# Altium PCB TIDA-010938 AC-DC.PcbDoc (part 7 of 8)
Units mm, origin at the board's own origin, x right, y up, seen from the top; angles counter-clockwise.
Board outline 280 x 180.15 mm, 4 copper layers (Top Layer, Layer 1, Layer 2, Bottom Layer), stack 1.787 mm thick; 723 components, 427 nets, 2244 pads, 2295 vias.
Unrouted connection lines stored in the file: 17.
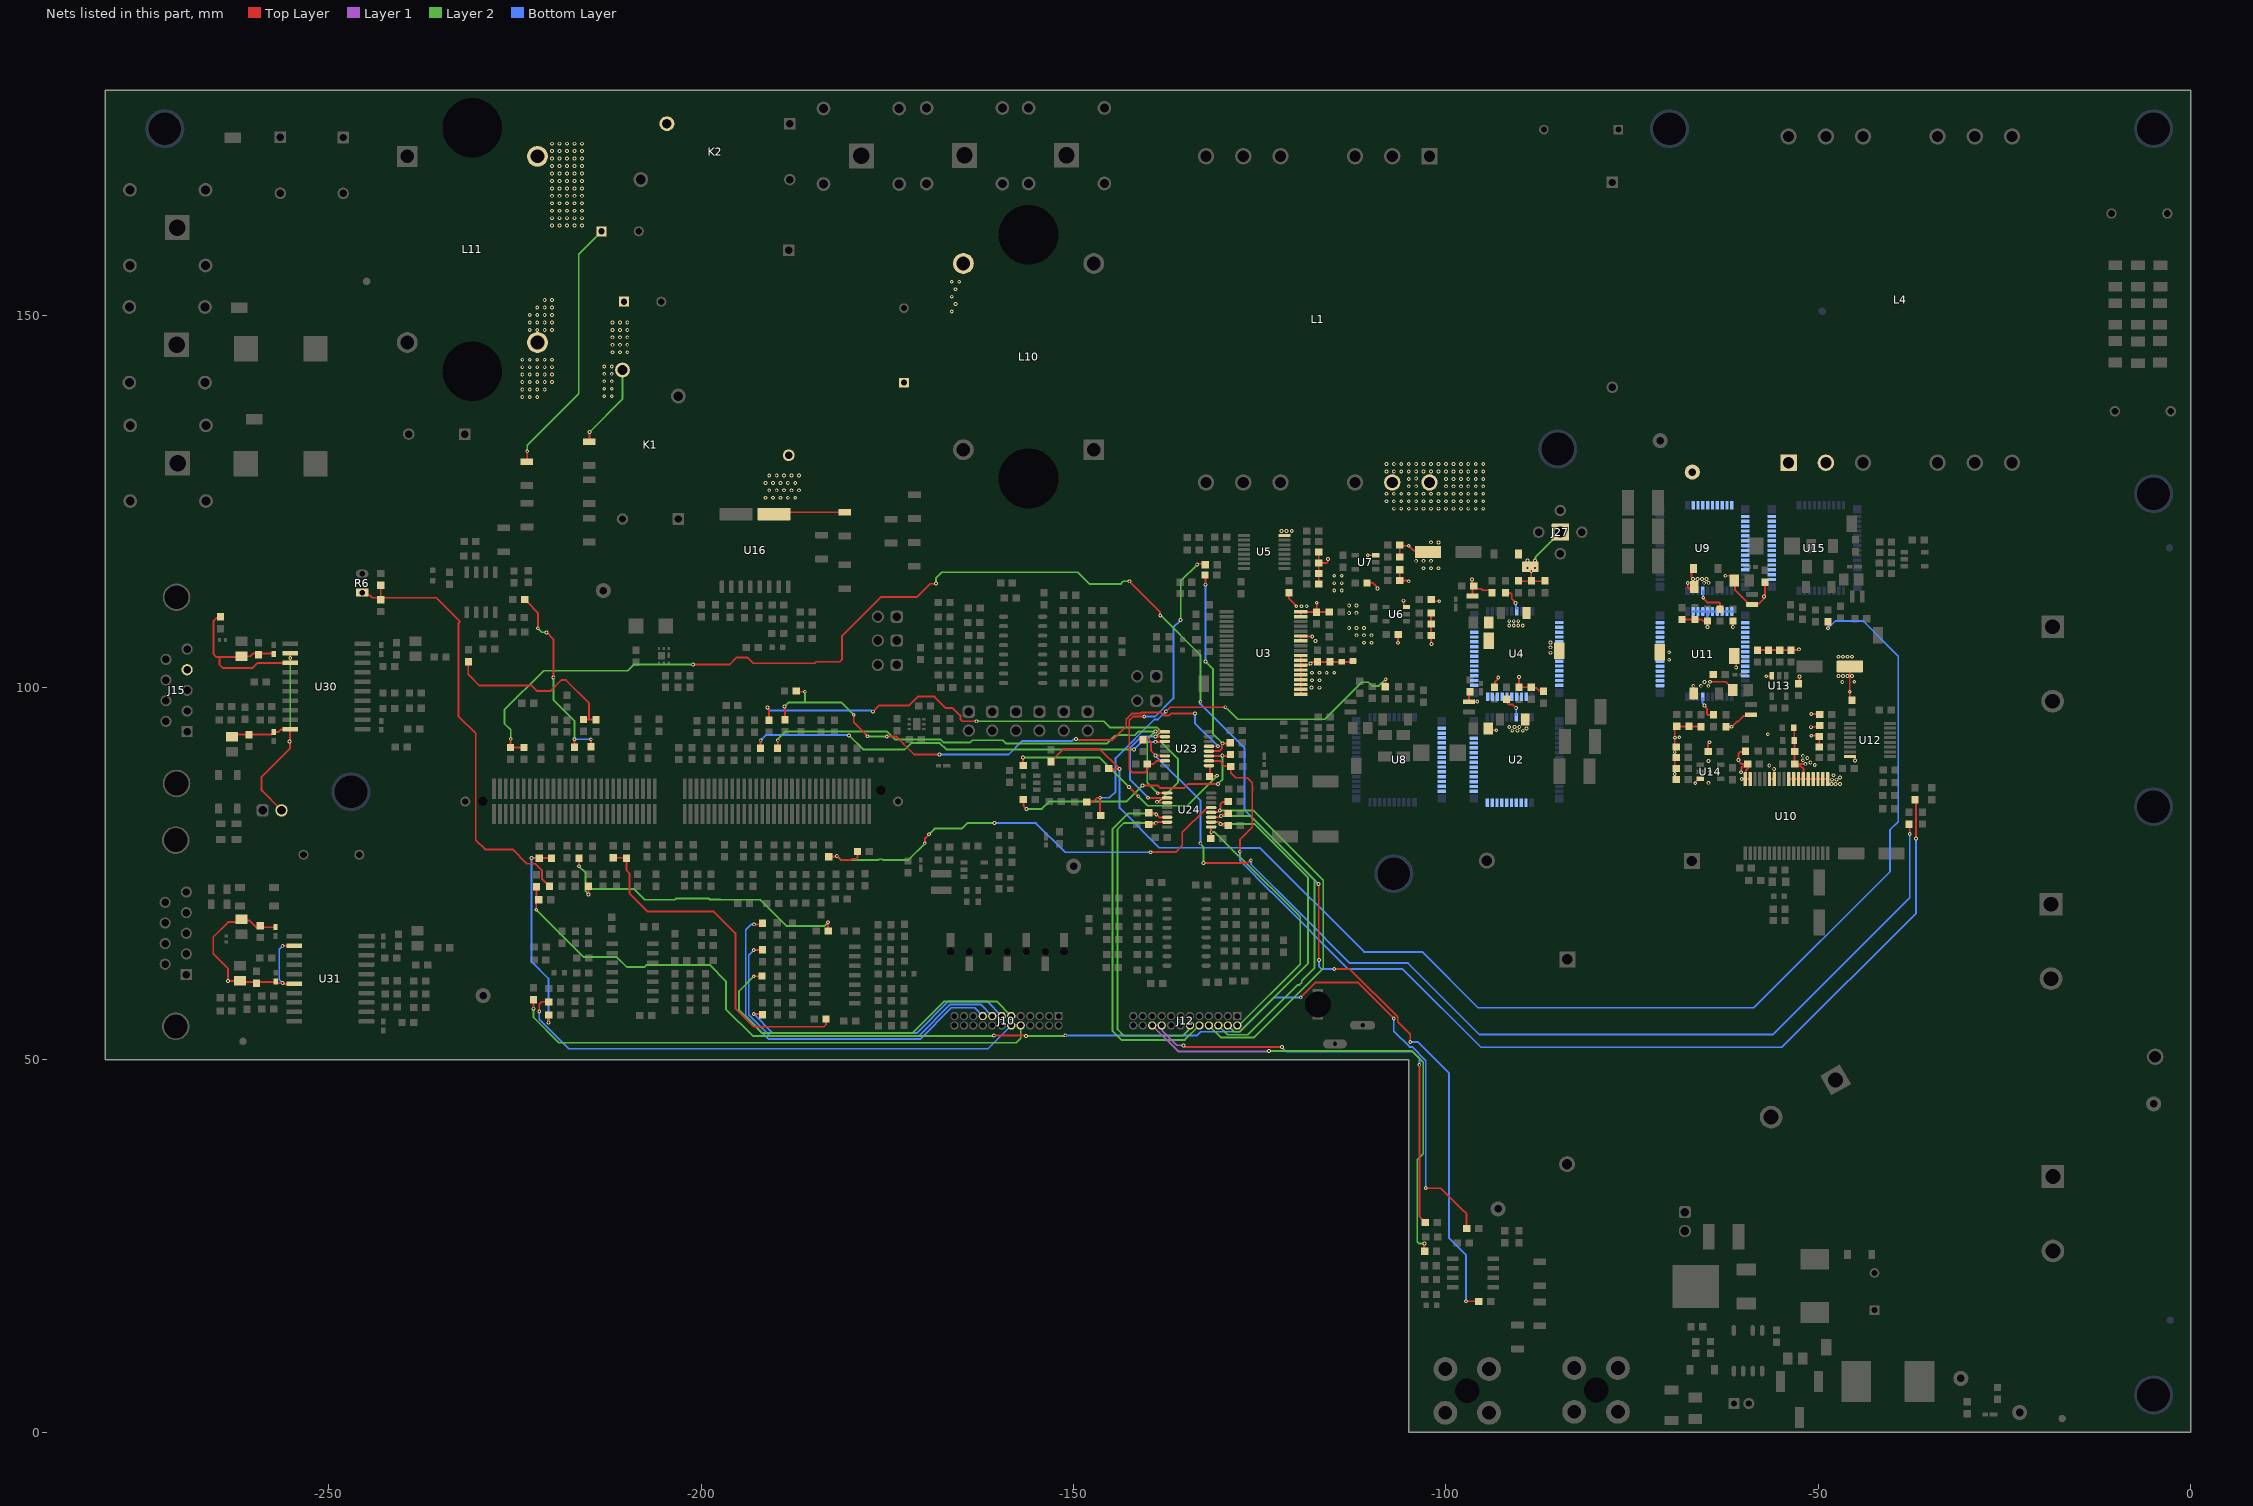
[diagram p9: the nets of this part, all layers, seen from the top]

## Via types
v1: diameter 0.508, hole 0.254, Top Layer to Bottom Layer, tented both sides, 2041 vias
v2: diameter 0.508, hole 0.254, Top Layer to Bottom Layer, 252 vias
v3: diameter 0.5, hole 0.2, Top Layer to Bottom Layer, 2 vias

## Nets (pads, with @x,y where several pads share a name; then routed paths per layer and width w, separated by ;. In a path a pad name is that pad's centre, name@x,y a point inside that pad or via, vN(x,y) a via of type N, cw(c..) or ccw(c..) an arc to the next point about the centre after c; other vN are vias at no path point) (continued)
SW_1: C11.2 C12.2 C13.1 C14.1 C15.2 C16.1 C17.1 C19.1 C20.2 C21.2 C24.2 C25.1 C26.2 C27.1 C28.2 C32.1 C33.1 C34.1 C35.1 C39.2 C40.2 C43.2 C47.2 C245.1 C246.1 C247.1 C248.1 D2.2 J27.1 L1.11 L1.12 L2.1 L3.1 R10.1 R15.2 R17.1 R30.1 R42.1 R237.1 R328.1 R329.1 R330.1 TP9.1 TP17.1 U2.18 U2.19 U2.20 U2.21 U2.22 U2.23 U2.24 U2.25 U2.26 U2.28 U2.29 U2.30 U2.31 U2.32 U2.33 U2.34 U2.35 U2.36 U2.37 U2.38 U2.39 U3.19 U3.20 U3.21 U3.22 U3.23 U3.24 U3.25 U3.26 U3.27 U3.30 U3.31 U3.35 U3.36 U4.18 U4.19 U4.20 U4.21 U4.22 U4.23 U4.24 U4.25 U4.26 U4.28 U4.29 U4.30 U4.31 U4.32 U4.33 U4.34 U4.35 U4.36 U4.37 U4.38 U4.39 U5.8 U6.3 U7.3 U8.2 U8.3 U8.4 U8.5 U8.6 U8.7 U8.8 U8.9 U8.10 U8.11 U8.12 U8.13 U8.14 U8.15 | length 73.3
  Top Layer w0.25: C39.2@-121.1,112.7 -121.1,111.95 -120.1,110.95 v1(-120.1,110.9) ; U3.27@-119.5,104.3 U3.26@-119.5,103.65 U3.25@-119.5,103 ; U3.35@-119.5,109.5 U3.36@-119.5,110.05 ; U3.36@-119.5,110.15 -117.55,110.15 C21.2@-117.475,110.225 ; U3.19@-119.425,99.175 -119.475,99.175 -119.5,99.2 U3.20@-119.5,99.75 U3.21@-119.5,100.4 U3.22@-119.5,101.05 U3.23@-119.5,101.7 U3.24@-119.5,102.35 U3.25@-119.5,103 ; U3.30@-119.425,106.3 -119.45,106.3 -119.5,106.35 U3.31@-119.5,106.9 -119.462,106.862 -117.962,106.862 v1@-117.95,106.85 ; v1(-117.35,111.375) -117.35,110.325 C21.2@-117.25,110.225 ; C21.2@-117.25,110.125 -115.775,110.125 R15.2@-115.725,110.175 ; C35.1@-117.075,118.2 C34.1@-117.075,116.7 ; C32.1@-117.05,113.9 -117.075,113.925 C33.1@-117.075,115.3 C34.1@-117.075,116.7 ; C16.1@-116.925,103.425 C17.1@-115.575,103.425 C19.1@-112.475,103.425 ; C16.1@-116.925,103.475 -116.979,103.421 -117.979,103.421 -118.35,103.05 -119.45,103.05 U3.25@-119.5,103 ; v1@-115.8,117.325 -115.874,117.251 -115.874,116.876 -116.05,116.7 C34.1@-117.075,116.7 ; C47.2@-110.6,114.05 -109.825,114.05 -109.249,113.474 -109.249,113.349 v1(-109.2,113.3) ; v1(-110.5,117.75) U7.3@-109.45,117.75 ; v1@-106.45,106.075 -106.45,107.05 C43.2@-106.4,107.1 ; C248.1@-106.2,117.525 R330.1@-106.2,119.125 -106.1,119.025 v1@-105.05,119.025 ; C247.1@-106.15,115.75 -106.2,115.7 R329.1@-106.2,114.35 -105.17,114.35 -105.07,114.25 v1(-105,114.25) ; v1(-105.72,111.65) -105.672,111.602 -105.672,110.975 -105.624,110.975 -105.449,110.8 U6.3@-105.3,110.8 ; v1(-105,119.025) -104.379,118.404 -102.604,118.404 C40.2@-102.4,118.2 ; C246.1@-102,110 C245.1@-102,108.5 R237.1@-102,107 -102,105.97 -101.98,105.95 v1@-101.95,105.95 ; R328.1@-102,111.8 -101.775,111.575 -101,111.575 v1@-100.925,111.65 ; R17.1@-96.8,99.4 -96.9,99.3 L2.1@-96.9,98.075 -96.887,98.088 -95.812,98.088 v1(-95.8,98.1) ; R17.1@-96.7,99.4 R17.1@-96.605,99.305 ; v1(-96.5,114.5) -96.5,113.8 R42.1@-96.3,113.6 ; L3.1@-96.45,112.275 -96.45,113.45 R42.1@-96.3,113.6 ; C28.2@-94.325,108.659 C28.2@-94.284,108.7 ; C15.2@-94.309,94.5 -94.059,94.25 v1(-93.254,94.25) ; C26.2@-93.8,112.7 -94.15,113.051 -95.046,113.051 -95.245,113.25 -95.95,113.25 R42.1@-96.3,113.6 ; C13.1@-93.475,100.05 -93.401,100.124 -93.401,100.779 v1@-92.992,101.187 ; D2.2@-90.36,117.998 D2.2@-90.262,117.9 ; R30.1@-90.25,114.325 -90.175,114.25 C27.1@-88.175,114.25 ; v1(-90.2,101.4) -90.2,100.225 -90.3,100.125 R10.1@-90.2,100.025 C14.1@-88.625,100.025 ; C11.2@-89.35,95.7 C11.2@-89.25,95.6 ; C24.2@-89.25,109.925 C24.2@-89.2,109.975 C24.2@-89.075,109.85 ; C14.1@-88.55,100.025 -88.475,99.95 -87.9,99.95 -87.55,99.6 -86.75,99.6 C12.2@-86.7,99.55 ; v1(-88.55,115.65) -88.55,114.625 C27.1@-88.175,114.25 ; C25.1@-86.75,114.25 C27.1@-88.175,114.25
  Layer 2 w0.25: v1(-88.046,117.051) -87.997,117.1 -87.997,117.511 J27.1@-84.654,120.853
  other v1: -91.1,94.2 -90.4,94.2 -89.7,94.2 -89.2,94.5 -91.5,94.7 -90.8,94.7 -90.15,94.7 -116.994,99.969 -118.048,100.002 -117.994,100.969 -116.994,100.969 -92.981,101.323 -117.994,101.969 -116.994,101.969 -116.019,101.969 -114.994,101.969 -118.175,103.2 -101.95,105.85 -111,106 -110,106 -106.45,106 -117.5,106.25 -117.95,106.825 -112,107 -111,107 -110,107 -113,108 -112,108 -111,108 -91.5,108.3 -90.9,108.3 -90.3,108.3 -89.7,108.3 -91.5,108.9 -90.9,108.9 -90.3,108.9 -113,110 -112.004,110.018 -119.4,110.9 -118.7,110.9 -113,111 -112,111 -100.9,111.575 -115,113 -114,113 -115,114 -114,114 -115,115 -114,115 -103,116 -102,116 -101,116 -89.046,116.051 -88.046,116.051 -104,117 -103,117 -102,117 -89.046,117.051 -115.825,117.25 -101.004,119.454 -102.028,119.482 -122.1,121 -121.4,121 -120.7,121 -107,124 -106,124 -105,124 -104,124 -103,124 -102,124 -101,124 -100,124 -99,124 -98,124 -97,124 -96,124 -95,124 -108,125 -107,125 -106,125 -105,125 -104,125 -103,125 -102,125 -101,125 -100,125 -99,125 -98,125 -97,125 -96,125 -95,125 -108,126 -107,126 -106,126 -105,126 -104,126 -103,126 -102,126 -101,126 -100,126 -99,126 -98,126 -97,126 -96,126 -95,126 -105,127 -104,127 -100,127 -99,127 -98,127 -97,127 -96,127 -95,127 -105,128 -100,128 -99,128 -98,128 -97,128 -96,128 -95,128 -104.002,128.039 -108,129 -107,129 -106,129 -105,129 -104,129 -103,129 -102,129 -101,129 -100,129 -99,129 -98,129 -97,129 -96,129 -95,129 -108,130 -107,130 -106,130 -105,130 -104,130 -103,130 -102,130 -101,130 -100,130 -99,130 -98,130 -97,130 -96,130 -95,130
SW_2: C44.2 C48.1 C57.2 C58.2 C59.1 C60.1 C61.2 C62.1 C63.1 C65.2 C66.2 C69.2 C70.1 C71.1 C72.1 C73.2 C77.1 C78.1 C79.1 C80.1 C85.1 C89.1 C91.2 C188.2 C240.2 C249.1 C250.1 D8.2 L4.1 L4.2 L6.1 L7.1 R33.1 R34.1 R44.1 R49.2 R51.1 R52.1 R60.1 R331.1 R332.1 TP10.1 TP18.1 U9.18 U9.19 U9.20 U9.21 U9.22 U9.23 U9.24 U9.25 U9.26 U9.28 U9.29 U9.30 U9.31 U9.32 U9.33 U9.34 U9.35 U9.36 U9.37 U9.38 U9.39 U10.19 U10.20 U10.21 U10.22 U10.23 U10.24 U10.25 U10.26 U10.27 U10.30 U10.31 U10.35 U10.36 U11.18 U11.19 U11.20 U11.21 U11.22 U11.23 U11.24 U11.25 U11.26 U11.28 U11.29 U11.30 U11.31 U11.32 U11.33 U11.34 U11.35 U11.36 U11.37 U11.38 U11.39 U12.8 U13.3 U14.3 U15.2 U15.3 U15.4 U15.5 U15.6 U15.7 U15.8 U15.9 U15.10 U15.11 U15.12 U15.13 U15.14 U15.15 | length 90.9
  Top Layer w0.25: R34.1@-69.39,87.621 -69.29,87.721 C70.1@-69.29,94.721 ; C70.1@-69.29,94.771 R60.1@-65.515,94.771 ; C58.2@-68.265,109.096 C58.2@-68.29,109.121 C60.1@-66.59,109.121 -65.69,109.121 -65.49,108.921 R44.1@-65.09,108.921 ; v1(-67.54,114.021) -67.54,113.471 -67.29,113.221 C57.2@-66.54,113.221 ; D8.2@-67.04,115.858 -67.04,114.815 -66.79,114.565 C57.2@-66.79,113.471 ; C69.2@-66.79,99.221 v1(-66.79,100.221) ; v1@-66.59,87.121 -66.59,87.221 -66.09,87.721 U14.3@-65.89,87.721 ; R44.1@-65.069,108.741 -64.89,108.562 v1(-64.89,108.121) ; C44.2@-64.815,91.396 -64.815,92.396 v1@-64.69,92.521 ; v1(-64.563,100.762) -62.432,100.762 -61.628,99.957 -61.628,99.792 C73.2@-61.481,99.646 ; R52.1@-64.29,101.521 R52.1@-64.09,101.721 ; v1(-62.5,115) -61.841,115 -61.731,114.89 C61.2@-61.731,114.446 ; C71.1@-62.39,94.721 v1(-61.665,94.721) -60.969,95.417 -60.796,95.417 -60.067,96.146 -59.715,96.146 -59.54,96.321 L7.1@-59.19,96.321 ; C61.2@-61.69,114.321 -61.221,113.852 -61.221,113.094 -59.565,111.438 -59.565,111.346 -59.365,111.146 L6.1@-58.89,111.146 -58.815,111.221 -58.04,111.221 -57.19,112.071 R51.1@-57.19,114.121 ; v1(-61.49,108.121) C59.1@-61.49,108.921 ; TP18.1@-61.29,104.221 -61.04,103.971 v1(-61.04,102.671) ; v1(-60.39,88.621) -60.341,88.67 -60.341,89.248 -60.194,89.394 -59.616,89.394 -59.465,89.546 -59.465,89.146 -59.765,88.846 -59.765,87.746 U10.36@-59.815,87.696 ; v1(-60.29,87.721) -59.84,87.721 U10.36@-59.815,87.696 ; R49.2@-59.79,91.421 -59.854,91.357 -60.481,91.357 -60.74,91.098 v1(-60.74,90.254) -60.74,90.196 -60.265,89.721 C66.2@-59.515,89.721 ; U10.35@-59.115,87.721 -59.14,87.696 U10.35@-59.165,87.696 U10.36@-59.815,87.696 ; R332.1@-57.79,105.021 C250.1@-56.69,105.021 C249.1@-55.19,105.021 R331.1@-53.69,105.021 -52.76,105.021 -52.66,105.121 v1(-52.59,105.121) ; v1(-57,101.5) -56.336,101.5 U13.3@-56.24,101.596 ; U10.31@-56.565,87.696 U10.30@-55.94,87.696 ; v1(-55.94,89.054) -55.928,89.042 -55.928,87.708 U10.30@-55.915,87.696 ; U10.30@-55.928,87.683 U10.30@-55.89,87.646 ; U10.27@-53.965,87.671 -53.94,87.696 U10.26@-53.315,87.696 U10.25@-52.665,87.696 ; C65.2@-53.265,92.871 -53.24,92.896 C188.2@-53.24,94.371 ; C63.1@-53.215,91.596 C65.2@-53.215,92.871 ; C62.1@-53.19,89.821 C63.1@-53.19,91.421 ; C62.1@-53.165,89.471 C62.1@-53.137,89.442 ; U10.25@-52.715,87.746 U10.25@-52.665,87.696 ; C91.2@-52.69,100.521 -52.54,100.671 v1(-52.54,101.471) ; U10.24@-52.015,88.296 -51.99,88.321 -51.99,89.071 -52.365,89.446 -52.915,89.446 C62.1@-53.19,89.721 -51.765,89.721 v1(-51.74,89.746) ; v1@-50.99,94.721 -50.015,94.721 C79.1@-49.84,94.896 ; v1@-50.915,96.421 -49.865,96.421 C80.1@-49.84,96.396 ; v1@-50.84,93.546 -50.04,93.546 C78.1@-49.89,93.396 ; C77.1@-49.89,91.996 C78.1@-49.89,93.321 ; U10.19@-48.715,87.696 U10.19@-48.765,87.696 U10.20@-49.415,87.696 U10.21@-50.065,87.696 U10.22@-50.715,87.696 U10.23@-51.365,87.696 U10.24@-52.015,87.696 U10.25@-52.665,87.696 ; C240.2@-45.79,103.121 C240.2@-45.79,102.821 v1(-45.79,99.425) -45.79,98.59 C85.1@-45.5,98.3 ; U12.8@-45.306,90.721 -45.194,90.721 -45.114,90.641 -45.114,90.218 v1(-45.09,90.193)
  Bottom Layer w0.25: U11.18@-66.825,110.196 U11.21@-64.875,110.196 ; v1(-64.89,108.121) -64.883,108.128 -64.883,110.188 U11.21@-64.875,110.196 ; U11.26@-61.625,110.196 U11.21@-64.875,110.196
  other v1: -48.24,87.021 -47.69,87.021 -47.09,87.021 -66.54,87.146 -64.765,87.196 -48.19,87.621 -47.59,87.621 -47.09,87.921 -47.99,88.221 -69.29,88.396 -64.515,88.671 -56.59,89.521 -50.49,89.6 -51.09,89.921 -64.765,90.117 -52.09,90.221 -51.49,90.521 -52.09,90.821 -69.29,91.313 -64.64,92.646 -69.24,93.246 -68.69,93.321 -50.965,93.521 -56.79,93.721 -50.99,94.671 -50.965,96.446 -65.79,100.221 -64.79,100.221 -65.29,100.721 -46.79,100.721 -45.19,100.771 -47.29,101.521 -46.69,101.521 -46.09,101.521 -45.49,101.521 -47.29,104.121 -46.69,104.121 -46.09,104.121 -45.49,104.121 -57.29,112.221 -65.34,114.046 -64.74,114.046 -66.84,114.546 -66.24,114.546 -65.64,114.546 -65.04,114.546
SW_mid: TP1.1 TP5.1 U4.2 U4.3 U4.4 U4.5 U4.6 U4.7 U4.8 U4.9 U4.10 U4.11 U4.12 U4.13 U4.14 U4.15 U11.2 U11.3 U11.4 U11.5 U11.6 U11.7 U11.8 U11.9 U11.10 U11.11 U11.12 U11.13 U11.14 U11.15
  other v1: -70.04,103.721 -85.95,104.673 -70.04,104.721 -85.95,105.385 -85.95,106.02
TEMP_ACDC: C129.1 R222.2 U23.5 | length 73.5
  Top Layer w0.25: v1(-188.8,97.43) -188.751,97.381 -188.751,97.081 R222.2@-188.75,95.65 ; C129.1@-187.2,99.5 -187.119,99.419 v1(-186.072,99.419) ; v1(-179.512,96.343) -179.512,95.318 v1(-177.644,93.45) ; v1@-175.129,93.421 -173.787,93.421 -172.825,92.459 -172.825,92.411 -171.414,91 v1(-168,91) ; v1(-149.673,93.079) -149.603,93.079 -149.474,92.95 -149.133,92.95 -149.121,92.939 -144.81,92.939 -142.929,94.819 -142.929,95.737 -142.166,96.5 -141,96.5 -140.871,96.629 -138.217,96.629 -137.827,96.239 -137.165,96.239 -136.889,96.516 v1(-133.675,96.516) ; U23.5@-131.825,92.1 v1(-130.6,92.1)
  Layer 2 w0.25: v1(-188.8,97.43) -188.271,97.959 -186,97.959 ; v1(-186.072,99.419) -186.072,98.031 -186,97.959 ; v1(-179.512,96.343) -181.129,97.959 -186,97.959 ; v1@-177.618,93.396 -177.615,93.399 v1(-175.079,93.399)
  Bottom Layer w0.25: v1(-168,91) -158.725,91 -156.9,92.825 -150.175,92.825 -149.97,93.03 -149.722,93.03 v1(-149.673,93.079) ; v1(-133.675,96.516) -133.716,96.474 -133.716,95.216 v1(-130.6,92.1)
TEMP_AMB_sense: C10.1 R5.1 R6.1 R182.2 | length 60.1
  Top Layer w0.25: R6.1@-245.5,112.73 -245.143,112.373 -244.47,112.373 -244.147,112.05 R5.1@-243,112.05 ; R5.1@-243,111.8 R5.1@-243,112.05 ; C10.1@-243,113.7 R5.1@-243,112.05 ; R182.2@-220.375,73.3 -220.375,73.325 -221.369,74.319 -221.369,75.442 -222.252,76.325 -223.375,76.325 -225.3,78.25 -229,78.25 -230.25,79.5 -230.25,93.83 -232.575,96.155 -232.575,108.589 -232.436,108.728 -232.436,108.936 -235.55,112.05 R5.1@-243,112.05
TEMP_Batt_H1_Buff: C177.2 J12.4 U24.2 | length 43.5
  Top Layer w0.25: U24.2@-131.525,81.925 -130.45,81.925 -129.975,81.45 C177.2@-129.45,81.45
  Layer 2 w0.25: v1@-130.25,81.75 -130.175,81.675 -125.741,81.675 -118.5,74.434 -118.5,62.954 -127.669,53.785 -128.45,53.785 J12.4@-129.285,54.62
  other v1: -130.275,81.675
TEMP_Batt_H2_Buff: C179.2 J12.12 U24.15 | length 45.2
  Top Layer w0.25: C179.2@-139.925,81.575 -139.15,81.575 -138.8,81.925 -137.992,81.925 -137.975,81.942 U24.15@-137.975,81.95
  Layer 2 w0.25: v1(-138.95,81.825) -143.225,81.825 -144.096,80.954 -144.096,54.096 -143.25,53.25 -135.347,53.25 -134.531,54.066 -134.531,54.544 J12.12@-134.5,54.575
TEMP_Batt_L1_Buff: C178.2 J12.2 U24.1 | length 36.2
  Top Layer w0.25: U24.1@-131.525,81.275 -131.525,79.975 C178.2@-131.45,79.9
  Layer 2 w0.25: v1(-131.5,80.575) -131.048,80.575 -127.894,77.421 -127.798,77.421 -119.571,69.194 -119.571,62.855 -127.806,54.62 J12.2@-128.015,54.62
TEMP_Batt_L2_Buff: C180.2 J12.10 U24.14 | length 49.6
  Top Layer w0.25: C180.2@-139.925,83.175 -139.125,83.175 -138.5,82.55 -137.45,82.55 U24.14@-137.425,82.575
  Layer 2 w0.25: v1@-138.925,83.075 -142.7,83.075 -144.75,81.025 -144.75,53.85 -143.575,52.675 -135.04,52.675 J12.10@-133.095,54.62
  other v1: -138.9,82.95
TEMP_Boost1_Buff: C174.2 J12.8 U24.4 | length 52.5
  Top Layer w0.25: U24.4@-131.525,83.225 -131.487,83.263 -130.637,83.263 -130.275,83.625 -130.275,84.325 -129.954,84.646 -129.479,84.646 C174.2@-129.45,84.675
  Layer 2 w0.25: J12.8@-131.825,54.62 -130.19,52.985 -125.815,52.985 -116.471,62.329 -116.471,74.119 -125.852,83.5 -130.275,83.5 v1@-130.325,83.55
  other v1: -130.375,83.5
TEMP_Boost2_Buff: C175.2 J12.6 U24.3 | length 47.2
  Top Layer w0.25: U24.3@-131.525,82.575 v1@-130.35,82.575 ; v1(-130.225,82.75) -130.175,82.75 -130,82.925 -129.575,82.925 -129.525,82.975 C175.2@-129.525,83.025
  Layer 2 w0.25: J12.6@-130.555,54.62 -129.32,53.385 -126.615,53.385 -119.929,60.071 -119.681,60.071 -119.371,60.381 -119.371,60.629 -117.629,62.371 -117.629,74.129 -126.25,82.75 v1(-130.225,82.75)
TEMP_DCDC: C138.1 R233.1 U24.5 | length 63.2
  Top Layer w0.25: R233.1@-182.86,77.251 -182.811,77.3 v1@-181.8,77.3 ; v1(-181.775,77.375) -181.246,76.846 -179.87,76.846 -179.716,77 -179.146,77 -179,77.146 C138.1@-179,78 ; v1(-169.975,79.075) -169.926,79.124 -169.926,79.774 v1(-169.4,80.3) ; v1@-139.6,77.9 -136.3,77.9 -135.4,78.8 -135.4,80.532 -132.207,83.725 -132.204,83.725 -132.054,83.875 U24.5@-131.525,83.875
  Layer 2 w0.25: v1(-181.775,77.375) -181.246,76.846 -176.193,76.846 -176.093,76.946 -175.655,76.946 -175.555,76.846 -172.154,76.846 v1@-169.9,79.1 ; v1(-169.4,80.3) -168.655,81.045 -165.005,81.045 -164.25,81.8 v1(-160.6,81.8)
  Bottom Layer w0.25: v1(-160.6,81.8) -155.052,81.8 -151.127,77.875 v1(-139.675,77.875)
TEMP_MUX_A: R216.2 U23.11 U24.11 | length 69.6
  Top Layer w0.25: R216.2@-192,92.1 v1(-192,92.9) ; v1@-138.9,92.8 -138.85,92.75 U23.11@-137.725,92.75 ; v1(-138.78,84.646) -138.711,84.646 -138.59,84.525 U24.11@-137.425,84.525
  Layer 2 w0.25: v1(-180.125,93.55) -178.256,91.681 -176.066,91.681 -176.033,91.648 -172.695,91.648 -171.804,92.539 -167.941,92.539 -167.083,91.681 v1(-141.871,91.681) ; v1(-139,92.7) -138.3,92.7 -136,90.4 -136,87.2 -138.505,84.695 -138.731,84.695 v1(-138.78,84.646)
  Bottom Layer w0.25: v1(-192,92.9) -191.3,93.6 v1@-180.1,93.6 ; v1(-141.871,91.681) -140.852,92.7 v1(-139,92.7)
TEMP_MUX_B: R218.2 U23.10 U24.10 | length 74.4
  Top Layer w0.25: v1(-191.1,97.3) -191.1,97.23 -190.9,97.03 -190.9,95.6 R218.2@-190.875,95.575 ; v1(-176.925,96.75) -176.082,97.593 -172.071,97.593 -170.885,98.779 -168.679,98.779 -167.137,97.237 -166.21,97.237 -165.196,96.222 -165.196,95.724 -164.926,95.455 v1(-163.035,95.455) ; v1(-140,85.2) -139.975,85.175 U24.10@-137.425,85.175 ; v1@-139,93.5 -138.9,93.4 U23.10@-137.725,93.4
  Layer 2 w0.25: v1(-163.035,95.455) -145.942,95.455 -145.129,94.642 -138.794,94.642 -138.471,94.319 -138.471,93.881 -138.952,93.4 v1(-139,93.4)
  Bottom Layer w0.25: v1(-191.1,97.3) -190.701,96.901 -177.146,96.901 -176.995,96.75 v1(-176.925,96.75) ; v1(-140,85.2) -142.4,87.6 -142.4,91.9 -140.9,93.4 v1(-139,93.4)
TEMP_MUX_C: R220.2 U23.9 U24.9 | length 65.9
  Top Layer w0.25: R220.2@-189.7,91.8 v1(-189.7,92.9) ; v1@-139.1,94.1 -139.075,94.075 -137.75,94.075 U23.9@-137.725,94.05 ; v1(-138.7,85.8) -138.687,85.813 -137.438,85.813 U24.9@-137.425,85.825
  Layer 2 w0.25: v1@-189.8,93 -188.721,94.079 -175.009,94.079 -173.93,93 -167.837,93 -167.445,92.608 -163.878,92.608 -163.577,92.909 -159.482,92.909 -159.073,92.5 -145.5,92.5 -144.529,93.471 -144.281,93.471 -144.132,93.62 -142.843,93.62 -142.807,93.584 -141.781,93.584 -141.265,94.1 v1(-139,94.1) ; v1@-139.048,94.1 -140.1,93.048 -140.1,87.2 v1(-138.7,85.8)
TEMP_S1: C167.2 R26.1 U23.4 | length 26.7
  Top Layer w0.25: R26.1@-132.35,115.075 -132.3,115.025 v1(-132.3,113.8) ; U23.4@-131.3,91.45 -130.45,91.45 -130.049,91.851 -130.049,92.451 v1(-130,92.5) -129.025,92.5 C167.2@-128.95,92.575
  Layer 2 w0.25: v1(-132.3,103.5) -131.3,102.5 -131.3,95.073 -131.296,95.069 -131.296,94.631 -131.3,94.627 -131.3,93.8 v1(-130,92.5)
  Bottom Layer w0.25: v1(-132.3,103.5) v1(-132.3,113.8)
TEMP_S1_init: R27.2 U2.49 | length 2.9
  Top Layer w0.25: R27.2@-91.85,98.425 -91.75,98.325 -91.75,97.896 -91.583,97.729 -91.079,97.729 -90.6,97.25 v1@-90.575,97.25
  Bottom Layer w0.25: U2.49@-90.575,96.325 -90.563,96.337 -90.563,97.213 v1(-90.575,97.225)
TEMP_S2: C168.2 R39.2 U23.3 | length 35.4
  Top Layer w0.25: R39.2@-156.721,84.966 -156.721,84.116 -156.325,83.72 v1(-156.325,83.7) ; v1(-140.725,86.85) -138.707,86.85 -138.353,86.496 -135.133,86.496 -134.579,87.05 v1(-130.613,87.05) ; U23.3@-131.425,90.8 -129.15,90.8 C168.2@-129,90.95
  Layer 2 w0.25: v1(-156.325,83.7) -154.25,83.7 -153.279,84.671 -142.904,84.671 v1(-140.725,86.85) ; v1(-130.613,87.05) -130.025,87.638 v1(-130.025,90.85)
TEMP_S2_init: C52.2 R37.1 R38.1 | length 54.7
  Top Layer w0.25: R38.1@-148.25,84.65 -147.358,84.65 -146.811,85.197 -146.428,85.197 v1(-146.425,85.2) C52.2@-146.425,82.9 ; v1(-137.608,96.768) -137.026,97.35 v1(-129.625,97.35) ; R37.1@-108.15,100.1 -108.1,100.15 v1(-108.1,101.1)
  Layer 2 w0.25: v1@-129.617,97.383 -129.617,97.369 -129.094,96.846 -129.08,96.846 -127.963,95.728 -116.272,95.728 -111.3,100.7 -110.4,100.7 -109.9,100.2 -109,100.2 v1(-108.1,101.1)
  Bottom Layer w0.25: v1(-146.425,85.2) -145.175,85.2 -144.346,86.029 -144.346,90.52 -139.166,95.7 -138.676,95.7 v1(-137.608,96.768)
TEMP_S3: C170.2 R61.1 U23.2 | length 142.3
  Top Layer w0.25: U23.2@-131.825,90.15 -130.427,90.15 ; -130.4,90.15 -129.675,89.425 C170.2@-129.05,89.425 ; C170.2@-128.9,89.375 -128.9,88.575 -128.2,87.875 -126.675,87.875 -126,87.2 -126,86.623 -125.971,86.594 -125.971,86.156 -126,86.127 -126,81.25 -127.675,79.575 -127.675,78.05 v1@-127.725,78 ; R61.1@-37.04,84.921 -36.89,84.771 -36.89,79.746 v1@-36.865,79.721
  Bottom Layer w0.25: v1(-127.675,77.95) -127.675,76.775 -123.43,72.53 -123.42,72.53 -123.11,72.22 -123.11,72.21 -113.1,62.2 -105.8,62.2 -95.3,51.7 -54.903,51.7 -36.89,69.713 v1(-36.89,79.721)
TEMP_S3_init: R62.2 U9.49 | length 4
  Top Layer w0.25: v1@-65.449,111.946 -65.465,111.946 -64.936,111.417 -63.337,111.417 -63.19,111.27 R62.2@-63.19,110.921
  Bottom Layer w0.25: U9.49@-65.525,112.996 -65.495,112.966 -65.495,111.976 v1@-65.465,111.946
  other v1: -65.465,112.046
TEMP_S4: C171.2 R73.2 U23.1 | length 34
  Top Layer w0.25: v1(-156.8,90.6) -156.8,89.525 R73.2@-156.775,89.5 ; v1(-142.566,86.639) -142.558,86.639 -141.309,85.391 v1(-141.301,85.391) ; U23.1@-131.825,89.5 -131.792,89.5 -131.7,89.408 C171.2@-131.7,88.275 ; C171.2@-131.75,88.05 -131.7,88.1 v1@-130.7,88.1
  Layer 2 w0.25: v1(-156.8,90.6) -146.527,90.6 v1(-142.566,86.639) ; v1@-141.296,85.395 -140.019,84.117 -134.758,84.117 v1(-130.725,88.15)
  Bottom Layer w0.25: v1(-156.8,90.6) v1@-156.751,90.649
TEMP_S4_init: C98.2 R71.1 R72.1 | length 182.1
  Top Layer w0.25: C98.2@-153.084,89.991 C98.2@-153.025,90.05 -153.025,90.075 -151.375,91.725 -146.471,91.725 v1(-143.817,89.071) -145.271,89.071 R72.1@-145.3,89.1 ; v1(-48.715,107.946) -48.715,108.771 R71.1@-48.69,108.796
  Bottom Layer w0.25: v1(-143.817,89.071) -143.825,89.063 -143.825,83.823 -138.481,78.479 -127.456,78.479 -127.402,78.425 -124.925,78.425 -111,64.5 -103.2,64.5 -95.7,57 -58.661,57 -40.39,75.271 -40.39,80.871 -39.282,81.979 -39.282,104.213 -43.99,108.921 -47.74,108.921 v1@-48.806,107.855
TEMP_S5: C172.2 R24.1 U23.15 | length 39.6
  Top Layer w0.25: v1(-140.5,96.1) -142,96.1 -142.529,95.571 -142.529,89.029 -142.1,88.6 -140.4,88.6 -140.075,88.925 C172.2@-140.075,89.725 -139.225,89.725 -138.8,90.15 -138.25,90.15 U23.15@-138.2,90.2 ; v1@-133.3,116.6 -132.45,116.6 R24.1@-132.325,116.475
  Layer 2 w0.25: v1@-135.6,109.1 -135.6,114.3 v1(-133.4,116.5)
  Bottom Layer w0.25: v1(-140.5,96.1) -139.024,96.1 -136.595,98.529 -136.595,108.08 -135.7,108.975 v1@-135.7,109.1
  other v1: -135.625,109.05
TEMP_S5_init: R25.2 U4.49 | length 3.1
  Top Layer w0.25: R25.2@-92,112.7 -91.975,112.675 -91.35,112.675 -91.162,112.487 -91.162,111.888 -90.722,111.447 -90.722,111.353 v1@-90.725,111.35
  Bottom Layer w0.25: v1(-90.65,111.35) -90.601,111.301 -90.601,110.675 -90.526,110.6 U4.49@-90.475,110.6
TEMP_S6: C173.2 R58.1 U23.14 | length 144
  Top Layer w0.25: C173.2@-140.7,93 -140.6,93.1 -140,93.1 -139.6,92.7 -139.6,91.5 -138.9,90.8 v1@-138.9,90.7 ; v1@-138.9,90.85 -138.2,90.85 U23.14@-138.15,90.9 ; v1(-132.57,76.446) -126.624,76.446 -126.27,76.8 v1(-126.2,76.8) ; R58.1@-37.84,81.646 -37.74,81.546 v1(-37.74,80.321)
  Layer 2 w0.25: v1@-132.95,79.1 -132.95,78.98 -132.57,78.6 v1(-132.57,76.446)
  Bottom Layer w0.25: v1(-139,90.85) -132.95,84.8 v1@-132.95,79.05 ; v1(-126.2,76.8) -126.2,76.3 -119.525,69.625 -112.9,63 -105.1,63 -95.5,53.4 -56.111,53.4 -37.74,71.771 v1(-37.74,80.321)
  other v1: -132.975,79.075
TEMP_S6_init: R59.2 U11.49 | length 3.2
  Top Layer w0.25: v1(-65.29,97.571) -65.29,97.501 -64.94,97.151 -64.94,96.446 -64.79,96.296 -64.315,96.296 R59.2@-64.265,96.246
  Bottom Layer w0.25: U11.49@-65.565,98.596 -65.54,98.571 -65.54,97.89 -65.29,97.64 v1(-65.29,97.571)
VAC_L: K1.3 L11.EII R75.1 R116.1 | length 11.5
  Top Layer w0.25: R116.1@-215,133 -214.975,133.025 v1(-214.975,134.296)
  Layer 2 w0.25: v1(-214.975,134.296) -210.553,138.717 K1.3@-210.553,142.613
  other v1: -224,139 -223,139 -222,139 -213,139.1 -212,139.1 -224,140 -223,140 -222,140 -221,140 -213,140.1 -212,140.1 -224,141 -223,141 -222,141 -221,141 -220,141 -213,141.1 -212,141.1 -224,142 -223,142 -222,142 -221,142 -220,142 -213,142.1 -212,142.1 -224,143 -223,143 -222,143 -221,143 -220,143 -213,143.1 -212,143.1 -224,144 -223,144 -222,144 -221,144 -220,144 -211.9,145 -210.9,145 -209.9,145 -211.9,146 -210.9,146 -209.9,146 -211.9,147 -210.9,147 -209.9,147 -223,148 -222,148 -221,148 -220,148 -211.9,148 -210.9,148 -209.9,148 -223,149 -222,149 -221,149 -220,149 -211.9,149 -210.9,149 -209.9,149 -223,150 -222,150 -221,150 -220,150 -222,151 -221,151 -220,151 -221,152 -220,152
VAC_N: K2.2 L11.EI R114.1 R127.1 | length 35.1
  Top Layer w0.25: R127.1@-223.4,130.3 -223.34,130.36 v1(-223.34,131.697)
  Layer 2 w0.25: v1(-223.34,131.697) -223.34,132.536 -216.429,139.446 -216.429,158.177 R114.1@-213.367,161.239
  other v1: -220,162 -219,162 -218,162 -217,162 -216,162 -220,163 -219,163 -218,163 -217,163 -216,163 -220,164 -219,164 -218,164 -217,164 -216,164 -220,165 -219,165 -218,165 -217,165 -216,165 -220,166 -219,166 -218,166 -217,166 -216,166 -220,167 -219,167 -218,167 -217,167 -216,167 -220,168 -219,168 -218,168 -217,168 -216,168 -220,169 -219,169 -218,169 -217,169 -216,169 -220,170 -219,170 -218,170 -217,170 -216,170 -220,171 -219,171 -218,171 -217,171 -216,171 -220,172 -219,172 -218,172 -217,172 -216,172 -220,173 -219,173 -218,173 -217,173 -216,173
VAC_sense: C132.2 R120.2 R178.1 | length 26
  Top Layer w0.25: R120.2@-223.669,111.785 -223.644,111.785 -223.294,111.435 -223.294,111.41 -221.916,110.033 v1(-221.916,107.95) ; v1(-220.748,107.391) -219.833,106.477 v1(-219.833,101.321) ; R178.1@-216.975,91.975 v1@-216.975,92.875 ; C132.2@-214.84,91.985 C132.2@-214.8,92.025 v1@-214.8,92.925
  Layer 2 w0.25: v1(-221.916,107.95) -221.377,107.411 -220.767,107.411 v1(-220.748,107.391) ; v1(-219.833,101.321) -219.833,98.333 -217,95.5 v1(-217,93.05)
  Bottom Layer w0.25: v1(-217,93.05) -214.85,93.05 v1@-214.775,92.975
  other v1: -214.8,93.05
VAC_SW+: C102.1 C104.2 L10.EII R111.1 U16.1 | length 9.6
  Top Layer w0.25: U16.1@-190.21,123.266 -189.956,123.52 R111.1@-180.717,123.52
  other v2: -191.352,125.464 -190.352,125.464 -189.352,125.464 -188.352,125.464 -187.352,125.464 -190.852,126.464 -189.852,126.464 -188.852,126.464 -187.852,126.464 -186.852,126.464 -191.352,127.464 -190.352,127.464 -189.352,127.464 -188.352,127.464 -187.352,127.464 -190.852,128.464 -189.852,128.464 -188.852,128.464 -187.852,128.464 -186.852,128.464 -166.352,150.464 -165.852,151.464 -166.352,152.464 -165.852,153.464 -166.352,154.464 -165.352,154.464
VDC_sense: C133.2 R1.2 R174.2 | length 222.4
  Top Layer w0.25: v1@-225.575,93.075 -225.565,93.065 C133.2@-225.565,91.939 -223.839,91.939 R174.2@-223.775,91.875 ; v1(-201.066,103.066) -196.184,103.066 -195.25,104 -193.75,104 -193,103.25 -184.757,103.25 -184.557,103.449 -181.383,103.449 -181.073,103.759 -181.073,106.934 -175.84,112.166 -170.979,112.166 -169.221,113.924 -168.494,113.924 v1(-168.467,113.951) ; v1(-142.5,114.25) -138.4,110.15 v1@-138.4,109.8 ; v1(-117.1,73.6) -117.08,73.58 -117.08,63.48 v1@-117,63.4 ; v1(-115,62.2) -112.889,62.2 -106.481,55.792 -106.481,55.132 -104.8,53.451 v1(-104.8,52.4) ; v1(-97.304,17.602) -95.602,17.602 R1.2@-95.575,17.575
  Layer 2 w0.25: v1(-225.55,93.1) -225.55,94.305 -226.404,95.159 -226.404,96.996 -221.15,102.25 -209.875,102.25 -209.059,103.066 v1(-201.066,103.066) ; v1(-168.467,113.951) -168.467,114.678 -167.67,115.475 -149.455,115.475 -147.88,113.9 -143.652,113.9 -143.302,114.25 v1(-142.5,114.25) ; v1@-138.301,109.683 -132.975,104.357 v1(-132.975,98.075)
  Bottom Layer w0.25: v1@-133,98.1 -133,97.8 -127.029,91.829 -127.029,83.529 v1(-117.1,73.6) ; v1(-117.06,63.423) -117.06,62.56 -116.7,62.2 v1(-115,62.2) ; v1(-104.8,52.4) -103.724,52.4 -99.6,48.276 -99.6,26.1 -97.304,23.804 v1(-97.304,17.602)
  other v1: -138.359,109.675
VIN_PWR_CAN: J15.4
Vinv_sense: C134.2 R121.2 R176.1 | length 24.7
  Top Layer w0.25: R121.2@-231.25,103.454 -231.25,101.75 -229.75,100.25 -222.75,100.25 -222,99.5 -220.25,99.5 -218.75,101 -218.152,101 -215.045,97.893 -215.045,95.7 ; R176.1@-215.8,95.7 R176.1@-215.683,95.7 ; R176.1@-215.683,95.817 -215.566,95.7 -215.045,95.7 ; -214.67,95.67 C134.2@-214.099,95.67 ; -214.67,95.7 -215.045,95.7
VP_CAN: C198.2 C205.1 C207.1 C210.2 C211.2 C212.1 C213.1 J16.2 U30.12 U30.13 U30.20 | length 57.4
  Top Layer w0.25: -264.7,104.075 -264.706,104.081 ; -264.652,104.081 -264.652,103.077 -264.175,102.6 -260.225,102.6 -259.523,103.302 U30.13@-255.156,103.302 v1(-255.156,103.937) U30.12@-255.156,104.572 ; C211.2@-264.506,109.312 -264.519,109.325 -265.075,109.325 -265.45,108.95 -265.45,104.45 -265.081,104.081 -264.706,104.081 ; C207.1@-262.982,93.65 -262.959,93.673 C198.2@-260.676,93.673 -257.717,93.673 -257.669,93.721 -257.569,93.721 -257.394,93.896 C205.1@-257.394,93.996 -256.754,93.996 -256.4,94.35 -256.075,94.35 U30.20@-256,94.425 ; C213.1@-262.45,104.1 -262.465,104.085 -264.701,104.085 -264.706,104.081 ; C213.1@-261.723,104.183 -260.548,104.183 -260.149,104.582 -259.718,104.582 C210.2@-259.7,104.6 ; C210.2@-259.437,104.572 -257.569,104.572 -257.525,104.528 C212.1@-257.525,104.475 ; J16.2@-256.33,83.5 -259,86.17 -259,88 -255.2,91.8 -255.2,92.75 U30.20@-255.2,94.4
  Layer 2 w0.25: v1(-255.25,92.75) -255.25,92.82 -255.156,92.914 v1(-255.156,103.937)
VP_RS485: C223.2 C224.1 C225.1 C226.2 C227.1 C228.1 U31.12 U31.16 | length 31.5
  Top Layer w0.25: C225.1@-261.9,60.6 v1(-263.5,60.6) -263.5,62.25 -265.5,64.25 -265.5,66.5 -263.497,68.503 -262.109,68.503 C228.1@-261.719,68.893 -261.526,68.7 -260.6,68.7 -259.7,67.8 -257.17,67.8 C227.1@-257.136,67.834 ; C225.1@-261.873,60.473 -259.7,60.473 C224.1@-257.227,60.473 ; C224.1@-257.1,60.5 -257.1,60.492 -256.925,60.317 v1(-256.174,60.317) ; v1@-256.125,60.2 U31.16@-255.5,60.2 ; v1@-256.071,65.329 U31.12@-254.62,65.329
  Bottom Layer w0.25: v1@-263.619,60.551 -263.5,60.67 v1@-263.5,60.7 ; v1(-256.174,60.317) -256.629,60.772 -256.629,64.862 v1(-256.174,65.317)
VS_Batt1: C152.2 R151.2 R183.2 | length 26.6
  Top Layer w0.25: v1(-222.75,77.1) C152.2@-221.725,77.1 R183.2@-220.075,77.1 ; v1@-220.475,55.05 -220.473,55.052 R151.2@-220.473,56.02
  Bottom Layer w0.25: v1(-222.75,77.1) -222.75,63.177 -220.5,60.927 v1@-220.5,55.05
  other v1: -220.5,55
VS_Batt1+: J10.10 R149.2 | length 71.1
  Top Layer w0.25: R149.2@-222.5,58.094 -222.5,56.975 v1@-222.475,56.95
  Layer 2 w0.25: v1@-222.5,56.85 -222.494,56.844 -222.494,55.694 -219.1,52.3 -157.7,52.3 -157.095,52.905 J10.10@-157.095,54.62
  other v1: -222.5,56.875
VS_Batt1-: J10.12 R153.2 | length 69.7
  Top Layer w0.25: v1(-221.725,56.5) -221.725,57.475 -221.402,57.798 R153.2@-220.473,57.798
  Bottom Layer w0.25: v1@-221.8,56.5 -221.725,56.425 -221.725,55.477 -217.748,51.5 -161.485,51.5 J10.12@-158.365,54.62
VS_Boost1: C157.2 R160.2 R186.1 | length 42.4
  Top Layer w0.25: v1@-216.363,76.137 C157.2@-216.363,77.101 ; v1(-215.119,72.194) R186.1@-215.119,73.328 ; R160.2@-182.975,67.475 -182.95,67.5 v1(-182.95,68.475)
  Layer 2 w0.25: v1(-216.4,76) -215.5,75.1 -215.5,72.922 ; v1(-215.119,72.194) -215.119,72.263 -215.5,72.645 -215.5,72.922 ; v1(-182.95,68.475) -183.425,68 -188.552,68 -192.052,71.5 -197.352,71.5 -197.381,71.529 -198.852,71.529 -199.002,71.679 -203.369,71.679 -203.548,71.5 -207.573,71.5 -208.996,72.922 -215.5,72.922
VS_Boost1+: J10.15 R158.2 | length 46.4
  Top Layer w0.25: v1(-192.925,64.75) -191.8,64.75 R158.2@-191.775,64.725
  Bottom Layer w0.25: v1@-192.95,64.725 -193.6,64.075 -193.6,56.077 -190.723,53.2 -170.775,53.2 -166.525,57.45 -162.465,57.45 J10.15@-160.905,55.89
VS_Boost1-: J10.17 R162.2 | length 49.5
  Top Layer w0.25: v1(-192.9,68.2) -191.7,68.2 R162.2@-191.675,68.225
  Bottom Layer w0.25: v1(-192.9,68.2) -193.297,68.2 -194,67.497 -194,55.911 -190.889,52.8 -170.609,52.8 -166.409,57 -163.285,57 J10.17@-162.175,55.89
VS_Boost2: C164.2 R169.2 R189.1 | length 47.2
  Top Layer w0.25: R189.1@-211.791,77.139 C164.2@-210.014,77.139 ; C164.2@-210.013,77.101 -210.013,75.436 -209.625,75.048 -209.625,72.375 -207.15,69.9 -198.275,69.9 -195.4,67.025 -195.4,56.95 -192.9,54.45 -183.5,54.45 -183.232,54.718 R169.2@-183.232,55.472
VS_Boost2+: J10.11 R168.2 | length 46.7
  Top Layer w0.25: v1(-192.925,61.225) R168.2@-191.825,61.225
  Layer 2 w0.25: v1@-193.05,61.1 -194.9,59.25 -194.9,56.65 -191.869,53.619 -171.581,53.619 -167.35,57.85 -160.325,57.85 J10.11@-158.365,55.89
VS_Boost2-: J10.13 R171.2 | length 38
  Top Layer w0.25: v1(-192.925,56.15) -191.95,56.15 R171.2@-191.925,56.125
  Bottom Layer w0.25: v1@-193,56.25 -190.35,53.6 -171.075,53.6 -166.825,57.85 -161.595,57.85 J10.13@-159.635,55.89
VS_DCDC_VDC+: J12.18 R135.2 | length 59.4
  Top Layer w0.25: v1(-135.25,51.92) -135.18,51.92 -134.99,51.73 v1(-122,51.73) ; v1@-103.552,49.428 -103.552,28.956 -103.165,28.569 -103.165,28.544 -102.815,28.194 R135.2@-102.79,28.194
  Layer 1 w0.25: J12.18@-138.175,54.62 -138.086,54.531 -138.086,53.886 -136.169,51.969 -135.299,51.969 v1(-135.25,51.92) ; v1@-122.035,51.765 v1(-122,51.73) ; v1@-103.577,49.453 v1@-103.552,49.428
  Bottom Layer w0.25: v1(-122,51.73) -122,51.66 -121.481,51.141 -104.527,51.141 -103.577,50.191 v1(-103.577,49.338)
VS_DCDC_VDC-: J12.20 R238.2 | length 65
  Top Layer w0.25: v1(-102.88,25.37) -102.88,25.3 -102.934,25.246 -102.934,24.375 R238.2@-102.871,24.311
  Layer 1 w0.25: J12.20@-139.445,54.62 -135.966,51.141 v1@-123.77,51.141
  Layer 2 w0.25: v1(-123.762,51.201) -104.588,51.201 -103.88,50.494 -103.048,49.662 -103.048,37.416 -103.859,36.605 -103.859,25.597 -103.632,25.37 v1(-102.88,25.37)
VS_DCDC_VDC_sense: C92.2 R67.2 R134.2 | length 166.7
  Top Layer w0.25: v1(-222.136,70.164) -222.136,71.164 C92.2@-222.119,71.181 ; R67.2@-222.119,73.228 C92.2@-222.119,71.181 ; C92.2@-221.8,71.5 C92.2@-222.119,71.181 ; v1(-160.7,53.266) -156.434,53.266 v1@-156.4,53.3 ; v1(-119.5,58.4) -117.5,60.4 -111.837,60.4 v1(-107.01,55.573) ; v1@-102.638,32.766 -100.701,32.766 -97.607,29.673 -97.577,29.673 -97.23,29.325 R134.2@-97.23,27.381 R134.2@-97.258,27.409
  Layer 2 w0.25: v1(-222.136,70.164) -215.772,63.8 -211.304,63.8 -209.975,62.471 -207.557,62.471 -207.274,62.754 -198.856,62.754 -196.668,60.567 -196.668,56.82 -193.068,53.219 -192.035,53.219 -160.746,53.219 v1(-160.7,53.266) ; v1(-156.4,53.2) -151.2,53.2 v1(-151.1,53.3)
  Bottom Layer w0.25: v1(-151.1,53.3) -133.406,53.3 -132.921,53.785 -127.669,53.785 -123.054,58.4 v1(-119.5,58.4) ; v1(-107.01,55.573) -107.01,53.862 -104.884,51.736 -104.557,51.736 -102.714,49.893 v1(-102.714,32.807)
pads on no net: FID1.1 FID2.1 FID3.1 FID4.1 FID5.1 FID6.1 J1.2 J1.3 J1.4 J1.5 J2.2 J2.3 J2.4 J2.5 J3.2 J3.3 J3.4 J3.5 J8. J8.6 J9.2 J9.3 J9.4 J9.5 J10.18 J10.19 J10.20 J10.21 J11.1 J11.2 J11.3 J11.4 J11.5 J11.6 J11.8 J11.9 J11.11 J11.14 J11.15 J11.17 J11.20 J11.32 J11.34 J11.36 J11.37 J11.41 J11.42 J11.43 J11.44 J11.45 J11.58 J11.60 J11.62 J11.64 J11.66 J11.71 J11.73 J11.85 J11.110 J11.113 J11.114 J11.115 J11.116 J11.117 J11.118 J11.119 J11.120 J11.181 J11.182 J11.185 J11.186 J12.22 J15.1 J15.8 J17.3 J17.4 J17.6 J17.7 J17.8 J17.9 J18. J19. J31.2 J31.3 J31.4 J31.5 J32.2 J32.3 J32.4 J32.5 L1.3 L1.4 L1.5 L1.6 L1.7 L1.8 L1.9 L1.10 L4.3 L4.4 L4.5 L4.6 L4.7 L4.8 L4.9 L4.10 L10. L11. LBL1.0 MP1. MP2. MP3. MP3.1 MP4. MP5. MP5.1 MP6. MP6.1 MP7. MP7.1 MP8. MP8.1 MP12. MP12.1 R6. R99.1 R125.2 R132.3 U2.1 U2.16 U2.17 U2.27 U2.43 U2.47 U2.52 U3.32 U4.1 U4.16 U4.17 U4.27 U4.43 U4.47 U4.52 U8.1 U8.16 U8.17 U8.27 U8.43 U8.47 U8.52 U9.1 U9.16 U9.17 U9.27 U9.43 U9.47 U9.52 U10.32 U11.1 U11.16 U11.17 U11.27 U11.43 U11.47 U11.52 U15.1 U15.16 U15.17 U15.27 U15.43 U15.47 U15.52 U16.10 U19.2 U19.5 U19.7@-171.06,94.626 U19.7@-171.06,95.526 U23.6 U24.6 U30.7

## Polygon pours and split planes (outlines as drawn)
"DC Bus-" on Bottom Layer "Bottom Layer-DC Bus-" (solid, pour order 284): 27 vertices, not listed, extent -82.4,109.472 -40,140.284
"DC Bus-" on Bottom Layer "BOTTOM_LAYER_DC_BUS-_P082" (solid, remove dead copper, pour order 82): 19 vertices, not listed, extent -113.8,81.75 -103.5,95.25
"DC Bus-" on Bottom Layer "Bottom Layer-DC Bus- 1" (solid, remove dead copper, pour order 124): 55 vertices, not listed, extent -246.652,16.561 -30.735,123.383
SW_2 on Bottom Layer "Bottom Layer-SW_2" (solid, pour order 282): 33 vertices, not listed, extent -68.5,97.003 -47.25,132.5
NetF2_1 on Bottom Layer "BOTTOM_LAYER_NETF2_1_P227" (solid, pour order 227): 25 vertices, not listed, extent -254.682,125.197 -228.952,174.625
VAC_N on Bottom Layer "BOTTOM_LAYER_VAC_N_P232" (solid, pour order 232): -225.142,177.622 -225.142,162.357 -220.595,157.81 -212,157.81 -212,165.039 -215.238,168.277 -215.238,171.704 -213.815,173.126 -202.358,173.126 -200.148,175.336 -200.148,177.851 -201.571,179.273 -223.491,179.273
"DC Bus-" on Bottom Layer "BOTTOM_LAYER_DC_BUS-_P362" (solid, remove dead copper, pour order 362): -72.5,1 -72.5,17.5 -78,17.5 -85,10.5 -85,1
"DC Bus+" on Bottom Layer "BOTTOM_LAYER_DC_BUS+_P066" (solid, remove dead copper, pour order 66): -70,125.5 -69.25,125.5 -69,125.75 -69,126.75 -69.372,127.122 -72.165,127.122 -72.715,126.572 -72.715,112.715 -72.5,112.5 -70,112.5 -70,115.5 -69,116.5 -69,121.357 -70,122.357
SW_1 on Bottom Layer "Bottom Layer-SW_1" (solid, remove dead copper, pour order 261): 30 vertices, not listed, extent -110,83 -87.75,130.5
VAC_SW+ on Bottom Layer "BOTTOM_LAYER_VAC_SW+_P353" (solid, remove dead copper, pour order 353): -192,125 -192,129.5 -189,132.5 -186.5,132.5 -186.5,129 -186,128.5 -186,125
"DC Bus-" on Bottom Layer "BOTTOM_LAYER_DC_BUS-_P350" (solid, remove dead copper, pour order 350): -79.5,98.75 -74.75,98.75 -71.75,95.75 -71.75,87 -68.75,84 -68.75,79.75 -79.5,79.75
NetC103_1 on Bottom Layer "BOTTOM_LAYER_NETC103_1_P328" (solid, remove dead copper, pour order 328): 25 vertices, not listed, extent -150,126 -8,177
ACLOAD_N on Bottom Layer "Bottom Layer-ACLOAD_N" (solid, pour order 280): 29 vertices, not listed, extent -209.8,128 -160,175
AC_L on Bottom Layer "BOTTOM_LAYER_AC_L_P324" (solid, pour order 324): -275.002,148.768 -275.002,145.009 -271.852,141.859 -259,141.859 -259,153.975 -261.388,153.975 -265.807,149.555 -274.189,149.555 -274.977,148.768
AC_N on Bottom Layer "BOTTOM_LAYER_AC_N_P213" (solid, pour order 213): -274.367,132.537 -274.367,128.778 -271.217,125.628 -259.372,125.628 -259,126 -259,132 -258,133 -258,137.795 -260.702,137.795 -265.172,133.325 -273.554,133.325 -274.342,132.537
PE2 on Bottom Layer "BOTTOM_LAYER_PE2_P273" (solid, pour order 273): -77.339,179.07 -67.509,179.07 -65.731,177.292 -65.731,174.519 -68,172.25 -76.25,172.25 -79.193,175.193 -79.193,177.216
PE3 on Bottom Layer "BOTTOM_LAYER_PE3_P289" (solid, pour order 289): -10.334,176.454 -8.073,178.714 -1.952,178.714 -0.631,177.394 -0.657,176.759 -0.657,132.359 -1.088,131.928 -3.171,131.928 -4.314,133.071 -4.314,140.614 -1.774,143.154 -1.774,159.004 -4.314,161.544 -4.314,169.564 -10.357,175.607
NetC229_1 on Bottom Layer "BOTTOM_LAYER_NETC229_1_P109" (solid, remove dead copper, pour order 109): -69.299,16.416 -69.571,16.688 -69.571,27.457 -69.112,27.916 -63.299,27.916 -63.299,16.416
PE on Bottom Layer "BOTTOM_LAYER_PE_P219" (solid, pour order 219): -278.294,174.516 -273.816,178.994 -249.196,178.994 -245.767,175.565 -245.767,173.025 -258.467,173.025 -265.223,166.268 -265.223,160.884 -268.347,157.759 -274.189,157.759 -278.294,161.864
ACLOAD_L on Bottom Layer "BOTTOM_LAYER_ACLOAD_L_P305" (solid, pour order 305): -206.625,155.321 -203.882,155.321 -203.857,155.296 -198.421,155.296 -195.932,152.806 -195.932,130.378 -193.062,127.508 -193.062,122.504 -197.913,122.504 -204.796,129.388 -204.796,148.996 -206.625,150.825
NetC103_2 on Bottom Layer "BOTTOM_LAYER_NETC103_2_P304" (solid, pour order 304): -150.771,158.801 -145.995,163.576 -117.424,163.576 -108,173 -101,173 -101,170 -121.445,149.555 -150.771,149.555
"DC Bus+" on Bottom Layer "BOTTOM_LAYER_DC_BUS+_P096" (solid, remove dead copper, pour order 96): -91.411,0.508 -102.728,0.508 -102.88,11.263 -102.386,11.633 -94.586,11.633 -83,23.219 -83,29.5 -85,31.5 -86,32.5 -86,39 -85,40 -75,40 -73,38 -73,26.056 -91.411,7.645
"DC Bus-" on Bottom Layer "BOTTOM_LAYER_DC_BUS-_P086" (solid, remove dead copper, pour order 86): -108.514,83.764 -100,75.25 -100,69.5 -93,62.5 -85.75,62.5 -74,62.5 -65.75,70.75 -65.75,82.25 -67.5,84 -75.5,84 -87.5,72 -95.25,72 -97.5,74.25 -97.5,78 -103.264,83.764
"DC Bus+" on Bottom Layer "BOTTOM_LAYER_DC_BUS+_P120" (solid, remove dead copper, pour order 120): -28.038,14 -28.038,55.187 -24.45,58.775 -24.45,113.75 -12.45,113.75 -12.45,14
NetF1_1 on Bottom Layer "BOTTOM_LAYER_NETF1_1_P276" (solid, pour order 276): -244.382,148.768 -238.299,148.768 -238.274,148.793 -236.572,147.091 -236.572,132.715 -238.731,130.556 -242.947,130.556 -245.944,133.553 -245.944,147.379
SW_mid on Bottom Layer "BOTTOM_LAYER_SW_MID_P059" (solid, remove dead copper, pour order 59): 17 vertices, not listed, extent -86.534,98.552 -69.491,110.287
VAC_L on Bottom Layer "BOTTOM_LAYER_VAC_L_P235" (solid, pour order 235): -225.027,149.239 -221.065,153.2 -209.216,153.2 -209.216,141.097 -211.604,138.709 -224.962,138.709
"DC Bus+" on Bottom Layer "BOTTOM_LAYER_DC_BUS+_P007" (solid, remove dead copper, pour order 7): -86.5,95.5 -85.5,96.5 -81.5,96.5 -81.5,81.25 -88.5,74.25 -95,74.25 -95.75,75 -95.75,78.75 -93.5,81 -88.75,81 -86.5,83.25
12V_HVN on Bottom Layer "BOTTOM_LAYER_12V_HVN_P182" (solid, remove dead copper, pour order 182): -41.531,25.317 -41.531,28.067 -38.781,28.067 -38.781,25.317
"DC Bus-" on Layer 1 "Layer 1-DC Bus-" (solid, pour order 374): 48 vertices, not listed, extent -246.634,16.586 -85.34,123.749
SW_1 on Layer 1 "Layer 1-SW_1" (solid, remove dead copper, pour order 57): 28 vertices, not listed, extent -122.5,93.5 -86.5,121.95
"DC Bus+" on Layer 1 "Layer 1-DC Bus+" (solid, remove dead copper, pour order 307): 56 vertices, not listed, extent -102.765,0.533 -1.342,130
VAC_N on Layer 1 "LAYER_1_VAC_N_P231" (solid, pour order 231): -225.142,177.648 -225.142,162.357 -220.595,157.81 -212,157.81 -212,165.039 -215.238,168.277 -215.238,171.704 -213.815,173.126 -202.358,173.126 -200.148,175.336 -200.148,177.851 -201.571,179.273 -223.516,179.273
NetF2_1 on Layer 1 "LAYER_1_NETF2_1_P226" (solid, pour order 226): 25 vertices, not listed, extent -254.682,125.197 -228.952,174.625
"DC Bus-" on Layer 1 "LAYER_1_DC_BUS-_P360" (solid, remove dead copper, pour order 360): -72.5,1 -72.5,17.5 -78,17.5 -86,9.5 -86,1
NetC229_1 on Layer 1 "LAYER_1_NETC229_1_P351" (solid, remove dead copper, pour order 351): -70,16.5 -70,27.5 -63,27.5 -63,16.5
"DC Bus-" on Layer 1 "LAYER_1_DC_BUS-_P346" (solid, remove dead copper, pour order 346): 18 vertices, not listed, extent -74,114 -40,139
"DC Bus-" on Layer 1 "LAYER_1_DC_BUS-_P345" (solid, remove dead copper, pour order 345): -102,79.5 -101,78.5 -99.5,78.5 -99.5,80 -106,86.5 -110,86.5 -110,93.612 -113.438,93.612 -114,93.05 -114,81.5 -112,79.5
SW_1 on Layer 1 "LAYER_1_SW_1_P338" (solid, remove dead copper, pour order 338): -109,125 -109,130 -108.5,130.5 -94,130.5 -94,123 -107,123
NetC103_2 on Layer 1 "LAYER_1_NETC103_2_P330" (solid, remove dead copper, pour order 330): -146,164 -117,164 -108,173 -101,173 -101,168 -104,165 -120,149 -151,149 -151,159 -151,149 -151,159
NetC103_1 on Layer 1 "LAYER_1_NETC103_1_P329" (solid, remove dead copper, pour order 329): 25 vertices, not listed, extent -150,126 -8,177
ACLOAD_N on Layer 1 "Layer 1-ACLOAD_N" (solid, pour order 301): 28 vertices, not listed, extent -209.319,128 -159,179.095
ACLOAD_L on Layer 1 "LAYER_1_ACLOAD_L_P326" (solid, remove dead copper, pour order 326): -197.706,125.006 -193.062,125.006 -193.062,127.508 -195.932,130.378 -195.932,153.632 -206.1,153.632 -206.1,150.3 -204.796,148.996 -204.8,148.993 -204.8,132.1 -198.6,125.9
AC_L on Layer 1 "LAYER_1_AC_L_P323" (solid, pour order 323): -275.002,148.768 -275.002,145.009 -271.852,141.859 -259,141.859 -259,153.975 -261.388,153.975 -265.807,149.555 -274.189,149.555 -274.977,148.768
AC_N on Layer 1 "LAYER_1_AC_N_P320" (solid, pour order 320): -274.367,132.537 -274.367,128.778 -271.217,125.628 -259.372,125.628 -259,126 -259,132 -258,133 -258,137.795 -260.702,137.795 -265.172,133.325 -273.554,133.325 -274.342,132.537
"DC Bus-" on Layer 1 "LAYER_1_DC_BUS-_P092" (solid, remove dead copper, pour order 92): 21 vertices, not listed, extent -70.696,0.305 -21.869,27.991
"DC Bus-" on Layer 1 "Layer 1-DC Bus- 1" (solid, remove dead copper, pour order 91): 34 vertices, not listed, extent -62,65 -31,121.363
NetC116_2 on Layer 1 "Layer 1-NetC116_2" (solid, pour order 319): 23 vertices, not listed, extent -67.946,3.099 -43.002,18.669
SW_2 on Layer 1 "LAYER_1_SW_2_P075" (solid, remove dead copper, pour order 75): 31 vertices, not listed, extent -69.776,86.6 -44.776,116.2
VAC_L on Layer 1 "LAYER_1_VAC_L_P234" (solid, pour order 234): -225.026,149.24 -221.065,153.2 -209.216,153.2 -209.216,141.097 -211.604,138.709 -224.961,138.709
VAC_N on Layer 1 "LAYER_1_VAC_N_P230" (solid, pour order 230): -225.142,177.648 -225.142,162.378 -220.649,157.885 -212.4,157.885 -212.4,165.461 -215.391,168.452 -215.391,171.779 -215.163,171.779 -213.74,173.202 -202.412,173.202 -200.202,175.411 -200.202,177.926 -201.624,179.348 -223.441,179.348
PE on Layer 1 "LAYER_1_PE_P216" (solid, pour order 216): -278.294,174.516 -273.816,178.994 -249.196,178.994 -245.767,175.565 -245.767,173.025 -246.63,172.161 -259.33,172.161 -265.223,166.268 -265.223,160.884 -268.347,157.759 -274.189,157.759 -278.294,161.864
GND_ISO_COMM on Layer 1 "LAYER_1_GND_ISO_COMM_P171" (solid, remove dead copper, pour order 171): -279.7,116.5 -277.4,118.8 -258.3,118.8 -253.6,114.1 -253.6,50.7 -278.3,50.7 -279.7,52.1
"DC Bus-" on Top Layer "TOP_LAYER_DC_BUS-_P203" (solid, remove dead copper, pour order 203): 32 vertices, not listed, extent -246.652,16.561 -85.34,123.266
"DC Bus-" on Top Layer "Top Layer-DC Bus-" (solid, remove dead copper, pour order 364): 32 vertices, not listed, extent -48.478,109.931 -41.25,122
"DC Bus-" on Top Layer "TOP_LAYER_DC_BUS-_P355" (solid, remove dead copper, pour order 355): -107.5,94.5 -104,94.5 -104,96.5 -107.5,96.5
3V3_HVN on Top Layer "TOP_LAYER_3V3_HVN_P180" (solid, remove dead copper, pour order 180): 45 vertices, not listed, extent -130.525,50.5 -103.25,94
"DC Bus+" on Top Layer "Top Layer-DC Bus+" (solid, pour order 372): 17 vertices, not listed, extent -96,74.5 -82.4,98.5
"DC Bus-" on Top Layer "Top Layer-DC Bus- 1" (solid, remove dead copper, pour order 368): 87 vertices, not listed, extent -114,0.61 -1.114,139
12V_HVN on Top Layer "TOP_LAYER_12V_HVN_P178" (solid, remove dead copper, pour order 178): -118.021,89.805 -114.271,89.805 -114.271,79.055 -114.521,78.805 -117.771,78.805 -118.021,79.055
SW_1 on Top Layer "TOP_LAYER_SW_1_P366" (solid, pour order 366): -117,107.25 -117,106.25 -117.25,106 -120.5,106 -120.5,107.25
"DC Bus+" on Top Layer "Top Layer-DC Bus+ 1" (solid, remove dead copper, pour order 365): -104.216,0.581 -91.161,0.581 -91.161,10.35 -89.35,10.35 -89.35,11.6 -91.35,11.6 -92.044,12.294 -104.216,12.294
NetF2_1 on Top Layer "TOP_LAYER_NETF2_1_P224" (solid, pour order 224): -254,131.753 -254,127.563 -251.634,125.197 -232.863,125.197 -228.952,129.108 -228.952,136.119 -229.892,137.058 -232.711,137.058 -233.75,136.019 -233.75,131.219 -236.369,128.6 -246.656,128.6 -249.831,131.775
AC_L on Top Layer "TOP_LAYER_AC_L_P212" (solid, pour order 212): -275.002,148.768 -275.002,145.009 -271.852,141.859 -259,141.859 -259,153.975 -261.388,153.975 -265.807,149.555 -274.189,149.555 -274.977,148.768
SW_1 on Top Layer "TOP_LAYER_SW_1_P357" (solid, remove dead copper, pour order 357): -109,105.5 -111.5,105.5 -112.5,106.5 -113.5,107.5 -113.5,111.5 -112,111.5 -111.5,111 -111.5,109 -111,108.5 -109.5,107 -109.5,106.5 -109,106
"DC Bus-" on Top Layer "TOP_LAYER_DC_BUS-_P356" (solid, remove dead copper, pour order 356): -107,101 -110.512,101 -110.512,102.488 -102.512,102.488 -102.5,102.5 -102.5,99 -103.1,99 -103.6,99.5 -107,99.5
"DC Bus-" on Top Layer "TOP_LAYER_DC_BUS-_P354" (solid, remove dead copper, pour order 354): -116,90.5 -114.5,90.5 -114.5,94 -114,94.5 -114,97.3 -113.525,97.775 -112,97.775 -112,98.5 -114.5,98.5 -116,97
PE3 on Top Layer "TOP_LAYER_PE3_P349" (solid, remove dead copper, pour order 349): -9,172 -9,178 -8,179 -2,179 -1,178 -1,163 -4,163 -4,167
PE2 on Top Layer "TOP_LAYER_PE2_P348" (solid, remove dead copper, pour order 348): -66,172 -76,172 -77.75,173.75 -77.75,176.25 -75,179 -67.439,179 -66,177.561
NetR109_2 on Top Layer "TOP_LAYER_NETR109_2_P341" (solid, remove dead copper, pour order 341): -89.35,17.25 -89.35,19.85 -85.1,19.85 -85.1,17.25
